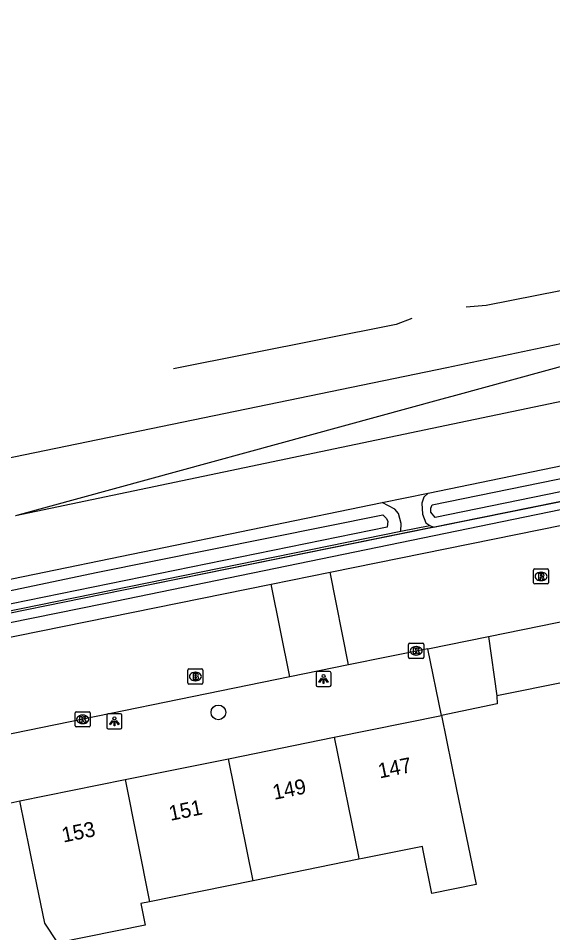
# Model space of a CAD drawing. Extents: x 162990 to 165007, y 383433 to 384336.
# Drawn here: x 163454.1 to 163489.5, y 384026.6 to 384087.3 of the extents above; entities that cross this region are included whole.
import ezdxf

# ---------------------------------------------------------------- set-up
doc = ezdxf.new("R2010")
doc.units = 0
for name, color, linetype in [('IMGEO_Berm_groen', 7, 'Continuous'), ('IMGEO_Boom', 7, 'Continuous'), ('IMGEO_Brandkraan', 7, 'Continuous'), ('IMGEO_Grasland_overig', 7, 'Continuous'), ('IMGEO_Greppel_droge_sloot', 7, 'Continuous'), ('IMGEO_Haag', 7, 'Continuous'), ('IMGEO_Hek', 7, 'Continuous'), ('IMGEO_Kolk', 7, 'Continuous'), ('IMGEO_Lichtpunt', 7, 'Continuous'), ('IMGEO_Pand', 7, 'Continuous'), ('IMGEO_Pand_nummerreeks', 7, 'Continuous'), ('IMGEO_Rijbaan_lokaal_gesloten', 7, 'Continuous'), ('IMGEO_Rijbaan_lokaal_open', 7, 'Continuous'), ('IMGEO_Rioolput', 7, 'Continuous'), ('IMGEO_Spoor', 7, 'Continuous'), ('IMGEO_Spoorbaan_halfverhard', 7, 'Continuous'), ('IMGEO_Voetpad_open', 7, 'Continuous')]:
    doc.layers.add(name, color=color, linetype=linetype)

msp = doc.modelspace()

# ---------------------------------------------------------------- linework, layer by layer
at = {"layer": 'IMGEO_Berm_groen'}
for points in [[(163432.67, 384043.744), (163479.459, 384053.271)], [(163479.459, 384053.271), (163481.381, 384053.662)]]:
    msp.add_lwpolyline(points, dxfattribs=at)
at = {"layer": 'IMGEO_Boom'}
msp.add_circle((163467.359, 384041.249), 0.489, dxfattribs=at)
at = {"layer": 'IMGEO_Brandkraan'}
for p, q in [((163465.409, 384044.134), (163466.261, 384044.134)), ((163465.334, 384043.208), (163465.334, 384044.06)), ((163465.822, 384043.914), (163465.847, 384043.914)), ((163466.335, 384044.06), (163466.335, 384043.208)), ((163466.261, 384043.134), (163465.409, 384043.134)), ((163465.845, 384043.354), (163465.82, 384043.354))]:
    msp.add_line(p, q, dxfattribs=at)
for points in [[(163465.409, 384044.134), (163466.261, 384044.134)], [(163465.334, 384043.208), (163465.334, 384044.06)], [(163465.682, 384043.834), (163465.682, 384043.434), (163465.895, 384043.434)], [(163465.913, 384043.834), (163465.682, 384043.834)], [(163465.861, 384043.753), (163465.807, 384043.753), (163465.807, 384043.677)], [(163465.807, 384043.677), (163465.86, 384043.677)], [(163465.869, 384043.601), (163465.807, 384043.601), (163465.807, 384043.52)], [(163465.807, 384043.52), (163465.869, 384043.52)], [(163466.335, 384044.06), (163466.335, 384043.208)], [(163466.261, 384043.134), (163465.409, 384043.134)]]:
    msp.add_lwpolyline(points, dxfattribs=at)
for centre, radius, start, end in [((163465.411, 384044.058), 0.0765, 91.55205, 178.44795), ((163465.411, 384044.058), 0.0765, 91.55205, 178.44795), ((163466.259, 384044.058), 0.0765, 1.55205, 88.44795), ((163466.259, 384044.058), 0.0765, 1.55205, 88.44795), ((163465.862, 384043.715), 0.0379, 267.82845, 90.93552), ((163465.87, 384043.56), 0.0404, 269.87594, 90.50774), ((163465.917, 384043.689), 0.145, 59.4692, 91.53667), ((163465.942, 384043.736), 0.0922, 285.51372, 58.15012), ((163465.947, 384043.544), 0.105, 301.31148, 78.98903), ((163465.411, 384043.21), 0.0765, 181.55205, 268.44795), ((163465.411, 384043.21), 0.0765, 181.55205, 268.44795), ((163465.901, 384043.685), 0.251, 268.66757, 293.53466), ((163466.259, 384043.21), 0.0765, 271.55205, 358.44795), ((163466.259, 384043.21), 0.0765, 271.55205, 358.44795)]:
    msp.add_arc(centre, radius, start, end, dxfattribs=at)
for centre, major_axis, ratio, start_param, end_param in [((163465.821, 384043.634), (-0.387, 0.002), 0.722429, 4.712389, 7.853982), ((163465.846, 384043.634), (-0.39, 0.002), 0.717154, 1.570796, 4.712389)]:
    msp.add_ellipse(centre, major_axis=major_axis, ratio=ratio, start_param=start_param, end_param=end_param, dxfattribs=at)
at = {"layer": 'IMGEO_Grasland_overig'}
msp.add_lwpolyline([(163479.459, 384053.271), (163479.481, 384053.775), (163479.296, 384054.442), (163479.052, 384054.743), (163478.222, 384055.178)], dxfattribs=at)
at = {"layer": 'IMGEO_Greppel_droge_sloot'}
for points in [[(163555.555, 384070.298), (163562.988, 384071.656), (163563.229, 384070.88), (163481.731, 384054.178), (163481.452, 384054.547), (163481.436, 384054.813), (163481.54, 384055.015), (163529.787, 384064.894), (163555.555, 384070.298)], [(163481.625, 384053.535), (163494.89, 384056.228), (163559.208, 384069.516), (163564.885, 384070.689)], [(163481.272, 384055.806), (163480.976, 384055.531), (163480.854, 384055.133), (163480.891, 384054.4), (163481.106, 384053.827), (163481.381, 384053.662)], [(163478.556, 384053.532), (163434.123, 384044.479), (163441.809, 384046.869), (163459.264, 384050.531), (163478.256, 384054.352), (163478.488, 384054.149), (163478.585, 384053.939), (163478.556, 384053.532)], [(163481.381, 384053.662), (163481.625, 384053.535)]]:
    msp.add_lwpolyline(points, dxfattribs=at)
at = {"layer": 'IMGEO_Haag'}
for points in [[(163408.734, 384037.023), (163409.522, 384037.258), (163419.713, 384040.294), (163422.158, 384040.849), (163459.771, 384048.486), (163651.736, 384088.019), (163830.895, 384125.387)], [(163481.625, 384053.535), (163459.651, 384049.074), (163442.263, 384045.543), (163422.031, 384041.436), (163419.561, 384040.874), (163408.564, 384037.598), (163408.734, 384037.023)]]:
    msp.add_lwpolyline(points, dxfattribs=at)
at = {"layer": 'IMGEO_Hek'}
for points in [[(163830.751, 384125.97), (163651.615, 384088.607), (163494.89, 384056.228), (163459.651, 384049.074)], [(163459.651, 384049.074), (163442.263, 384045.543)]]:
    msp.add_lwpolyline(points, dxfattribs=at)
at = {"layer": 'IMGEO_Kolk'}
for p, q in [((163479.974, 384044.91), (163479.974, 384045.762)), ((163480.049, 384045.836), (163480.901, 384045.836)), ((163480.462, 384045.616), (163480.487, 384045.616)), ((163480.975, 384045.762), (163480.975, 384044.91)), ((163480.901, 384044.836), (163480.049, 384044.836)), ((163480.485, 384045.056), (163480.46, 384045.056)), ((163457.862, 384040.362), (163457.862, 384041.214)), ((163457.937, 384041.288), (163458.789, 384041.288)), ((163458.35, 384041.068), (163458.375, 384041.068)), ((163458.863, 384041.214), (163458.863, 384040.362)), ((163458.373, 384040.508), (163458.348, 384040.508)), ((163458.789, 384040.288), (163457.937, 384040.288))]:
    msp.add_line(p, q, dxfattribs=at)
for points in [[(163479.974, 384044.91), (163479.974, 384045.762)], [(163480.049, 384045.836), (163480.901, 384045.836)], [(163480.295, 384045.536), (163480.418, 384045.536), (163480.418, 384045.385), (163480.548, 384045.536), (163480.712, 384045.536), (163480.566, 384045.385), (163480.719, 384045.136), (163480.567, 384045.136), (163480.482, 384045.3), (163480.418, 384045.233), (163480.418, 384045.136), (163480.295, 384045.136), (163480.295, 384045.536)], [(163480.975, 384045.762), (163480.975, 384044.91)], [(163480.901, 384044.836), (163480.049, 384044.836)], [(163457.862, 384040.362), (163457.862, 384041.214)], [(163457.937, 384041.288), (163458.789, 384041.288)], [(163458.863, 384041.214), (163458.863, 384040.362)], [(163458.183, 384040.988), (163458.306, 384040.988), (163458.306, 384040.837), (163458.436, 384040.988), (163458.6, 384040.988), (163458.454, 384040.837), (163458.607, 384040.588), (163458.455, 384040.588), (163458.37, 384040.752), (163458.306, 384040.685), (163458.306, 384040.588), (163458.183, 384040.588), (163458.183, 384040.988)], [(163458.789, 384040.288), (163457.937, 384040.288)]]:
    msp.add_lwpolyline(points, dxfattribs=at)
for centre, start, end in [((163480.051, 384045.76), 91.55205, 178.44795), ((163480.051, 384045.76), 91.55205, 178.44795), ((163480.899, 384045.76), 1.55205, 88.44795), ((163480.899, 384045.76), 1.55205, 88.44795), ((163480.051, 384044.912), 181.55205, 268.44795), ((163480.051, 384044.912), 181.55205, 268.44795), ((163480.899, 384044.912), 271.55205, 358.44795), ((163480.899, 384044.912), 271.55205, 358.44795), ((163457.939, 384041.212), 91.55205, 178.44795), ((163457.939, 384041.212), 91.55205, 178.44795), ((163458.787, 384041.212), 1.55205, 88.44795), ((163458.787, 384041.212), 1.55205, 88.44795), ((163457.939, 384040.364), 181.55205, 268.44795), ((163457.939, 384040.364), 181.55205, 268.44795), ((163458.787, 384040.364), 271.55205, 358.44795), ((163458.787, 384040.364), 271.55205, 358.44795)]:
    msp.add_arc(centre, 0.0765, start, end, dxfattribs=at)
for centre, major_axis, ratio, start_param, end_param in [((163480.461, 384045.336), (-0.387, 0.002), 0.722429, 4.712389, 7.853982), ((163480.486, 384045.336), (-0.39, 0.002), 0.717154, 1.570796, 4.712389), ((163458.349, 384040.788), (-0.387, 0.002), 0.722429, 4.712389, 7.853982), ((163458.374, 384040.788), (-0.39, 0.002), 0.717154, 1.570796, 4.712389)]:
    msp.add_ellipse(centre, major_axis=major_axis, ratio=ratio, start_param=start_param, end_param=end_param, dxfattribs=at)
at = {"layer": 'IMGEO_Lichtpunt'}
for p, q in [((163473.833, 384043.864), (163473.833, 384043.057)), ((163473.833, 384043.864), (163473.833, 384043.057)), ((163474.735, 384043.959), (163473.927, 384043.959)), ((163474.735, 384043.959), (163473.927, 384043.959)), ((163474.829, 384043.057), (163474.829, 384043.864)), ((163474.829, 384043.057), (163474.829, 384043.864)), ((163473.927, 384042.963), (163474.735, 384042.963)), ((163473.927, 384042.963), (163474.735, 384042.963)), ((163459.967, 384041.057), (163459.967, 384040.25)), ((163459.967, 384041.057), (163459.967, 384040.25)), ((163460.869, 384041.152), (163460.061, 384041.152)), ((163460.869, 384041.152), (163460.061, 384041.152)), ((163460.963, 384040.25), (163460.963, 384041.057)), ((163460.963, 384040.25), (163460.963, 384041.057)), ((163460.061, 384040.156), (163460.869, 384040.156)), ((163460.061, 384040.156), (163460.869, 384040.156))]:
    msp.add_line(p, q, dxfattribs=at)
for points in [[(163474.207, 384043.528), (163474.246, 384043.5), (163474.058, 384043.238), (163474.02, 384043.265), (163474.207, 384043.528)], [(163474.309, 384043.48), (163474.356, 384043.48), (163474.356, 384043.158), (163474.309, 384043.158), (163474.309, 384043.48)], [(163474.419, 384043.5), (163474.457, 384043.527), (163474.644, 384043.265), (163474.605, 384043.237), (163474.419, 384043.5)], [(163460.341, 384040.721), (163460.38, 384040.693), (163460.192, 384040.431), (163460.154, 384040.458), (163460.341, 384040.721)], [(163460.443, 384040.673), (163460.49, 384040.673), (163460.49, 384040.351), (163460.443, 384040.351), (163460.443, 384040.673)], [(163460.553, 384040.693), (163460.591, 384040.72), (163460.778, 384040.458), (163460.739, 384040.43), (163460.553, 384040.693)]]:
    msp.add_lwpolyline(points, dxfattribs=at)
for centre in [(163474.332, 384043.662), (163460.466, 384040.855)]:
    msp.add_circle(centre, 0.0994, dxfattribs=at)
for centre, start, end in [((163473.927, 384043.864), 90, 180), ((163473.927, 384043.864), 90, 180), ((163474.735, 384043.864), 0, 90), ((163474.735, 384043.864), 0, 90), ((163473.927, 384043.057), 180, 270), ((163473.927, 384043.057), 180, 270), ((163474.735, 384043.057), 270, 0), ((163474.735, 384043.057), 270, 360), ((163460.061, 384041.057), 90, 180), ((163460.061, 384041.057), 90, 180), ((163460.869, 384041.057), 0, 90), ((163460.869, 384041.057), 0, 90), ((163460.061, 384040.25), 180, 270), ((163460.061, 384040.25), 180, 270), ((163460.869, 384040.25), 270, 0), ((163460.869, 384040.25), 270, 360)]:
    msp.add_arc(centre, 0.0946, start, end, dxfattribs=at)
at = {"layer": 'IMGEO_Pand'}
for points in [[(163475.037, 384039.596), (163482.158, 384041.04)], [(163482.158, 384041.04), (163483.151, 384036.14), (163484.447, 384029.827), (163481.519, 384029.227), (163480.918, 384032.197), (163480.886, 384032.353), (163476.921, 384031.55), (163476.678, 384031.5)], [(163468.032, 384038.176), (163475.037, 384039.596)], [(163475.037, 384039.596), (163476.642, 384031.678), (163476.678, 384031.5)], [(163461.173, 384036.786), (163468.032, 384038.176)], [(163469.673, 384030.08), (163468.032, 384038.176)], [(163454.196, 384035.371), (163461.173, 384036.786)], [(163461.173, 384036.786), (163462.793, 384028.685)], [(163462.793, 384028.685), (163462.215, 384028.568), (163462.506, 384027.135), (163456.714, 384025.961), (163455.847, 384027.273), (163455.189, 384030.471), (163454.196, 384035.371)], [(163476.678, 384031.5), (163469.673, 384030.08)], [(163469.673, 384030.08), (163462.793, 384028.685)]]:
    msp.add_lwpolyline(points, dxfattribs=at)
at = {"layer": 'IMGEO_Rijbaan_lokaal_gesloten'}
for points in [[(163474.78, 384050.554), (163569.015, 384069.685)], [(163410.773, 384036.455), (163412.582, 384037.103), (163414.405, 384037.712), (163416.239, 384038.284), (163418.085, 384038.817), (163419.942, 384039.312), (163421.809, 384039.768), (163423.331, 384040.11), (163470.865, 384049.76)], [(163485.275, 384046.295), (163500, 384049.301), (163501.629, 384049.627)], [(163481.25, 384045.474), (163485.275, 384046.295)], [(163481.25, 384045.474), (163475.982, 384044.399)], [(163472.098, 384043.606), (163452.88, 384039.683)]]:
    msp.add_lwpolyline(points, dxfattribs=at)
at = {"layer": 'IMGEO_Rijbaan_lokaal_open'}
for points in [[(163470.865, 384049.76), (163474.78, 384050.554)], [(163475.982, 384044.399), (163474.78, 384050.554)], [(163472.098, 384043.606), (163470.865, 384049.76)], [(163475.982, 384044.399), (163472.098, 384043.606)]]:
    msp.add_lwpolyline(points, dxfattribs=at)
at = {"layer": 'IMGEO_Rioolput'}
for p, q in [((163488.33, 384050.772), (163489.182, 384050.772)), ((163488.255, 384049.846), (163488.255, 384050.698)), ((163488.743, 384050.552), (163488.768, 384050.552)), ((163489.256, 384050.698), (163489.256, 384049.846)), ((163489.182, 384049.772), (163488.33, 384049.772)), ((163488.766, 384049.992), (163488.741, 384049.992))]:
    msp.add_line(p, q, dxfattribs=at)
for points in [[(163488.33, 384050.772), (163489.182, 384050.772)], [(163488.255, 384049.846), (163488.255, 384050.698)], [(163488.844, 384050.47), (163488.592, 384050.472), (163488.592, 384050.072)], [(163488.592, 384050.072), (163488.716, 384050.072), (163488.716, 384050.234), (163488.727, 384050.234)], [(163488.77, 384050.391), (163488.716, 384050.391), (163488.716, 384050.31)], [(163488.716, 384050.31), (163488.768, 384050.31)], [(163488.774, 384050.205), (163488.845, 384050.072), (163488.985, 384050.072), (163488.92, 384050.198)], [(163489.256, 384050.698), (163489.256, 384049.846)], [(163489.182, 384049.772), (163488.33, 384049.772)]]:
    msp.add_lwpolyline(points, dxfattribs=at)
for centre, radius, start, end in [((163488.332, 384050.696), 0.0765, 91.55205, 178.44795), ((163488.332, 384050.696), 0.0765, 91.55205, 178.44795), ((163489.18, 384050.696), 0.0765, 1.55205, 88.44795), ((163489.18, 384050.696), 0.0765, 1.55205, 88.44795), ((163488.726, 384050.181), 0.0533, 26.02933, 88.69889), ((163488.752, 384050.499), 0.19, 274.7715, 282.96867), ((163488.776, 384050.295), 0.0964, 77.00612, 93.18647), ((163488.79, 384050.352), 0.0378, 276.66336, 79.67722), ((163488.843, 384050.36), 0.109, 350.36119, 89.41601), ((163488.841, 384050.36), 0.112, 277.58423, 350.98172), ((163488.825, 384050.145), 0.108, 29.51342, 73.79051), ((163488.332, 384049.848), 0.0765, 181.55205, 268.44795), ((163488.332, 384049.848), 0.0765, 181.55205, 268.44795), ((163489.18, 384049.848), 0.0765, 271.55205, 358.44795), ((163489.18, 384049.848), 0.0765, 271.55205, 358.44795)]:
    msp.add_arc(centre, radius, start, end, dxfattribs=at)
for centre, major_axis, ratio, start_param, end_param in [((163488.742, 384050.272), (-0.387, 0.002), 0.722429, 4.712389, 7.853982), ((163488.767, 384050.272), (-0.39, 0.002), 0.717154, 1.570796, 4.712389)]:
    msp.add_ellipse(centre, major_axis=major_axis, ratio=ratio, start_param=start_param, end_param=end_param, dxfattribs=at)
at = {"layer": 'IMGEO_Spoor'}
for points in [[(163575.669, 384079.775), (163482.894, 384060.374)], [(163514.005, 384070.749), (163482.504, 384064.124)], [(163514.005, 384070.749), (163483.077, 384062.28)], [(163482.504, 384064.124), (163438.347, 384055.003), (163304.284, 384027.02), (163290.651, 384024.258), (163275.14, 384021.273), (163261.909, 384018.846), (163250.276, 384016.868), (163239.034, 384015.076), (163225.051, 384013.191), (163210.675, 384011.424), (163197.565, 384010.035), (163186.306, 384009.051), (163170.778, 384007.955), (163157.742, 384007.242), (163145.353, 384006.773), (163136.4, 384006.585), (163127.534, 384006.532), (163114.97, 384006.669), (163093.304, 384007.27), (163079.785, 384007.903), (163066.124, 384008.71), (163050.352, 384009.854), (163020.285, 384012.339), (163007.925, 384013.445)], [(163482.179, 384062.042), (163453.899, 384054.293)], [(163483.077, 384062.28), (163482.179, 384062.042)], [(163482.894, 384060.374), (163453.899, 384054.293)]]:
    msp.add_lwpolyline(points, dxfattribs=at)
at = {"layer": 'IMGEO_Spoorbaan_halfverhard'}
for points in [[(163529.295, 384077.717), (163528.462, 384077.141), (163512.279, 384073.997), (163500.004, 384071.187), (163485.116, 384068.256), (163483.781, 384068.146)], [(163480.177, 384067.387), (163479.156, 384066.999), (163464.376, 384064.059)], [(163481.272, 384055.806), (163496.482, 384058.939)], [(163478.222, 384055.178), (163481.272, 384055.806)], [(163441.356, 384047.511), (163446.456, 384048.636), (163478.222, 384055.178)]]:
    msp.add_lwpolyline(points, dxfattribs=at)
at = {"layer": 'IMGEO_Voetpad_open'}
for points in [[(163485.275, 384046.295), (163485.829, 384042.347)], [(163482.158, 384041.04), (163481.25, 384045.474)], [(163502.447, 384045.7), (163500, 384045.203), (163485.829, 384042.347)], [(163485.829, 384042.347), (163485.854, 384041.829), (163482.158, 384041.04)], [(163410.036, 384026.962), (163450.636, 384035.203), (163450.784, 384034.639), (163454.196, 384035.371)]]:
    msp.add_lwpolyline(points, dxfattribs=at)

# ---------------------------------------------------------------- texts
at = {"layer": 'IMGEO_Pand_nummerreeks'}
for s, rotation, p in [('147', 11.45916, (163478.053, 384036.861)), ('149', 11.45916, (163471.062, 384035.444)), ('151', 11.46078, (163464.184, 384034.05)), ('153', 11.46078, (163457.081, 384032.609))]:
    msp.add_text(s, height=1, rotation=rotation, dxfattribs=at).set_placement(p)

doc.saveas('drawing.dxf')
